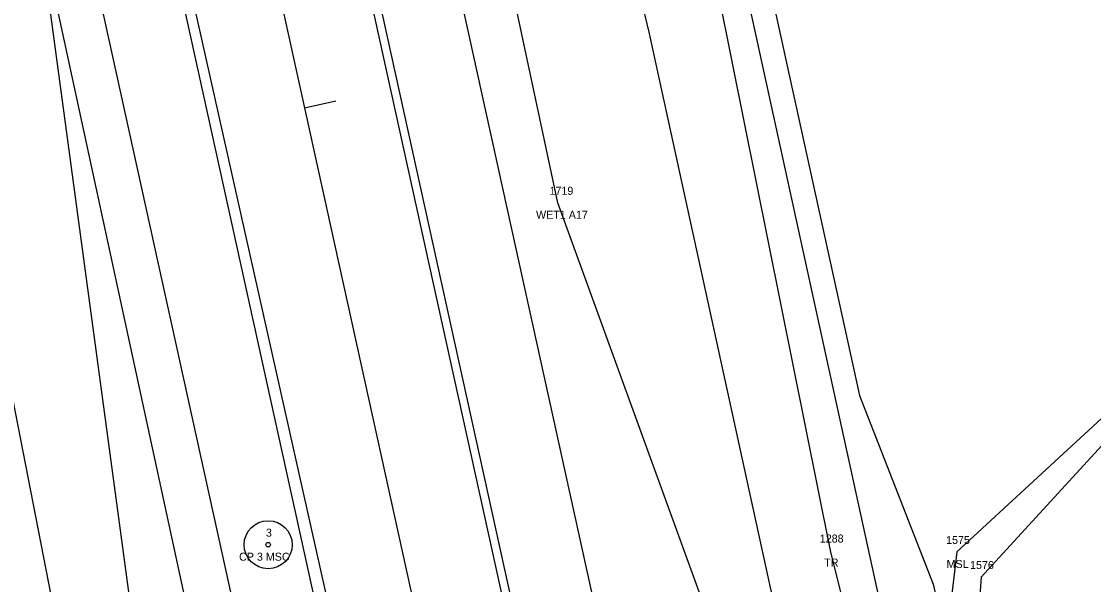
# Model space of a CAD drawing. Extents: x 2521558 to 2524785, y 882711 to 887632.
# Drawn here: x 2523710.8 to 2523844.7, y 885257.9 to 885328.2 of the extents above; entities that cross this region are included whole.
import ezdxf

# ---------------------------------------------------------------- set-up
doc = ezdxf.new("R2010")
doc.units = 0
for name, color, linetype in [('RD_EV_JW', 7, 'Continuous'), ('RD_EX_H2O', 7, 'Continuous'), ('RD_EX_H2O_txCode', 7, 'Continuous'), ('RD_EX_H2O_WetLd_txCode', 7, 'Continuous'), ('RD_EX_Misc', 7, 'Continuous'), ('RD_EX_Misc_txCode', 7, 'Continuous'), ('RD_EX_Road', 7, 'Continuous'), ('RD_EX_VEG', 7, 'Continuous'), ('RD_EX_VEG_txCode', 7, 'Continuous'), ('RD_HC_Cl', 7, 'Continuous'), ('RD_HC_Data', 7, 'Continuous'), ('RD_HC_Data_Tic', 7, 'Continuous'), ('RD_HC_txCode', 7, 'Continuous'), ('RD_PD_BCA', 7, 'Continuous'), ('RD_PD_CstnLmt', 7, 'Continuous'), ('RD_PD_DR_ErosCtrl', 7, 'Continuous'), ('RD_PD_Final_TrvlWay', 7, 'Continuous'), ('RD_PD_GR', 7, 'Continuous'), ('RD_PD_RW', 7, 'Continuous'), ('RD_SMD_Locator', 7, 'Continuous')]:
    doc.layers.add(name, color=color, linetype=linetype)

msp = doc.modelspace()

# ---------------------------------------------------------------- linework, layer by layer
at = {"layer": 'RD_EV_JW'}
for points in [[(2523761.17, 885134.03), (2523740.58, 885149.03), (2523730.55, 885209.77), (2523710.6, 885357.47), (2523698.09, 885411.19), (2523674.93, 885498.62), (2523657.6, 885564.24), (2523640.82, 885610.87), (2523583.66, 885726.91), (2523539.21, 885693.17), (2523494.42, 885646.98)], [(2523761.17, 885134.03), (2523808.21, 885149.21), (2523821.91, 885178.64), (2523802.85, 885236.55), (2523777.81, 885305.56), (2523748.2, 885444.32), (2523730.68, 885516.88), (2523708.64, 885617.3), (2523698.71, 885662.02), (2523727.83, 885665.82), (2523757.3, 885671.75)]]:
    msp.add_lwpolyline(points, dxfattribs=at)
at = {"layer": 'RD_EX_H2O'}
msp.add_lwpolyline([(2524064.86, 885165.15), (2524036.37, 885213.78), (2524057.22, 885252.72), (2524031.95, 885291.63), (2523983.25, 885326.3), (2523940.61, 885311.83), (2523904.84, 885305.01), (2523874.98, 885272.1), (2523850.32, 885280.24), (2523830.66, 885258.8), (2523826.93, 885206.61)], dxfattribs=at)
at = {"layer": 'RD_EX_Misc'}
msp.add_lwpolyline([(2524066.31, 885165.35), (2524037.3, 885214.15), (2524057.95, 885253.07), (2524039.52, 885283.17), (2524032.92, 885292.57), (2523983.53, 885327.98), (2523940.24, 885313.27), (2523904.13, 885306.25), (2523874.86, 885272.67), (2523849.96, 885282.51), (2523827.65, 885261.93), (2523821.38, 885209.28)], dxfattribs=at)
at = {"layer": 'RD_EX_Road'}
for p, q in [((2523771.24, 885254.79), (2523751.35, 885344.92)), ((2523750.32, 885250.18), (2523730.02, 885340.63))]:
    msp.add_line(p, q, dxfattribs=at)
at = {"layer": 'RD_EX_VEG'}
for points in [[(2523825.62, 885207.01), (2523811.87, 885262.11), (2523733.02, 885654.22), (2523687.11, 885876.24)], [(2523749.81, 885158.06), (2523732.86, 885248.57), (2523691.62, 885438.95), (2523639.52, 885601.04)]]:
    msp.add_lwpolyline(points, dxfattribs=at)
at = {"layer": 'RD_HC_Cl'}
msp.add_line((2523641.17, 885794.2), (2524197.76, 883266.56), dxfattribs=at)
at = {"layer": 'RD_HC_Data'}
for radius in [3, 0.282]:
    msp.add_circle((2523741.6, 885262.84), radius, dxfattribs=at)
at = {"layer": 'RD_HC_Data_Tic'}
msp.add_line((2523746.15, 885317.42), (2523750.06, 885318.28), dxfattribs=at)
at = {"layer": 'RD_PD_BCA'}
for p, q in [((2523815.5, 885281.49), (2523824.7, 885257.92)), ((2523824.7, 885257.92), (2523830.05, 885233.47))]:
    msp.add_line(p, q, dxfattribs=at)
at = {"layer": 'RD_PD_CstnLmt'}
for p, q in [((2523766.59, 885424.32), (2523789.14, 885326.89)), ((2523789.14, 885326.89), (2523810.51, 885229.2)), ((2523704.35, 885308.21), (2523723.51, 885210.04))]:
    msp.add_line(p, q, dxfattribs=at)
at = {"layer": 'RD_PD_DR_ErosCtrl'}
msp.add_line((2523801.84, 885329.66), (2523823.21, 885231.97), dxfattribs=at)
at = {"layer": 'RD_PD_Final_TrvlWay'}
for p, q in [((2523741.74, 885393.25), (2524015.93, 884148.08)), ((2523718.31, 885388.09), (2523992.49, 884142.92))]:
    msp.add_line(p, q, dxfattribs=at)
at = {"layer": 'RD_PD_GR'}
for p, q in [((2523742.1, 885438.13), (2523790.49, 885218.39)), ((2523747.52, 885208.93), (2523699.13, 885428.66))]:
    msp.add_line(p, q, dxfattribs=at)
at = {"layer": 'RD_PD_RW'}
msp.add_line((2523767.12, 885501.23), (2523815.5, 885281.49), dxfattribs=at)
at = {"layer": 'RD_SMD_Locator'}
for centre in [(2523777.81, 885305.56), (2523741.6, 885262.84), (2523811.87, 885262.11), (2523827.65, 885261.93), (2523830.66, 885258.8)]:
    msp.add_circle(centre, 0.001, dxfattribs=at)

# ---------------------------------------------------------------- texts
at = {"layer": 'RD_EX_H2O_txCode'}
msp.add_text('1576', height=1, dxfattribs=at).set_placement((2523829.29, 885259.8))
at = {"layer": 'RD_EX_H2O_WetLd_txCode'}
for s, p in [('1719', (2523776.75, 885306.56)), ('WET1 A17', (2523775.07, 885303.56))]:
    msp.add_text(s, height=1, dxfattribs=at).set_placement(p)
at = {"layer": 'RD_EX_Misc_txCode'}
for s, p in [('1575', (2523826.3, 885262.93)), ('MSL', (2523826.36, 885259.93))]:
    msp.add_text(s, height=1, dxfattribs=at).set_placement(p)
at = {"layer": 'RD_EX_VEG_txCode'}
for s, p in [('1288', (2523810.52, 885263.11)), ('TR', (2523811.07, 885260.11))]:
    msp.add_text(s, height=1, dxfattribs=at).set_placement(p)
at = {"layer": 'RD_HC_txCode'}
for s, p in [('3', (2523741.32, 885263.84)), ('CP 3 MSC', (2523737.97, 885260.84))]:
    msp.add_text(s, height=1, dxfattribs=at).set_placement(p)

doc.saveas('drawing.dxf')
